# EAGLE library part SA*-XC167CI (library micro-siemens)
16bit Microcontroller with MAC Unit 256KB Flash
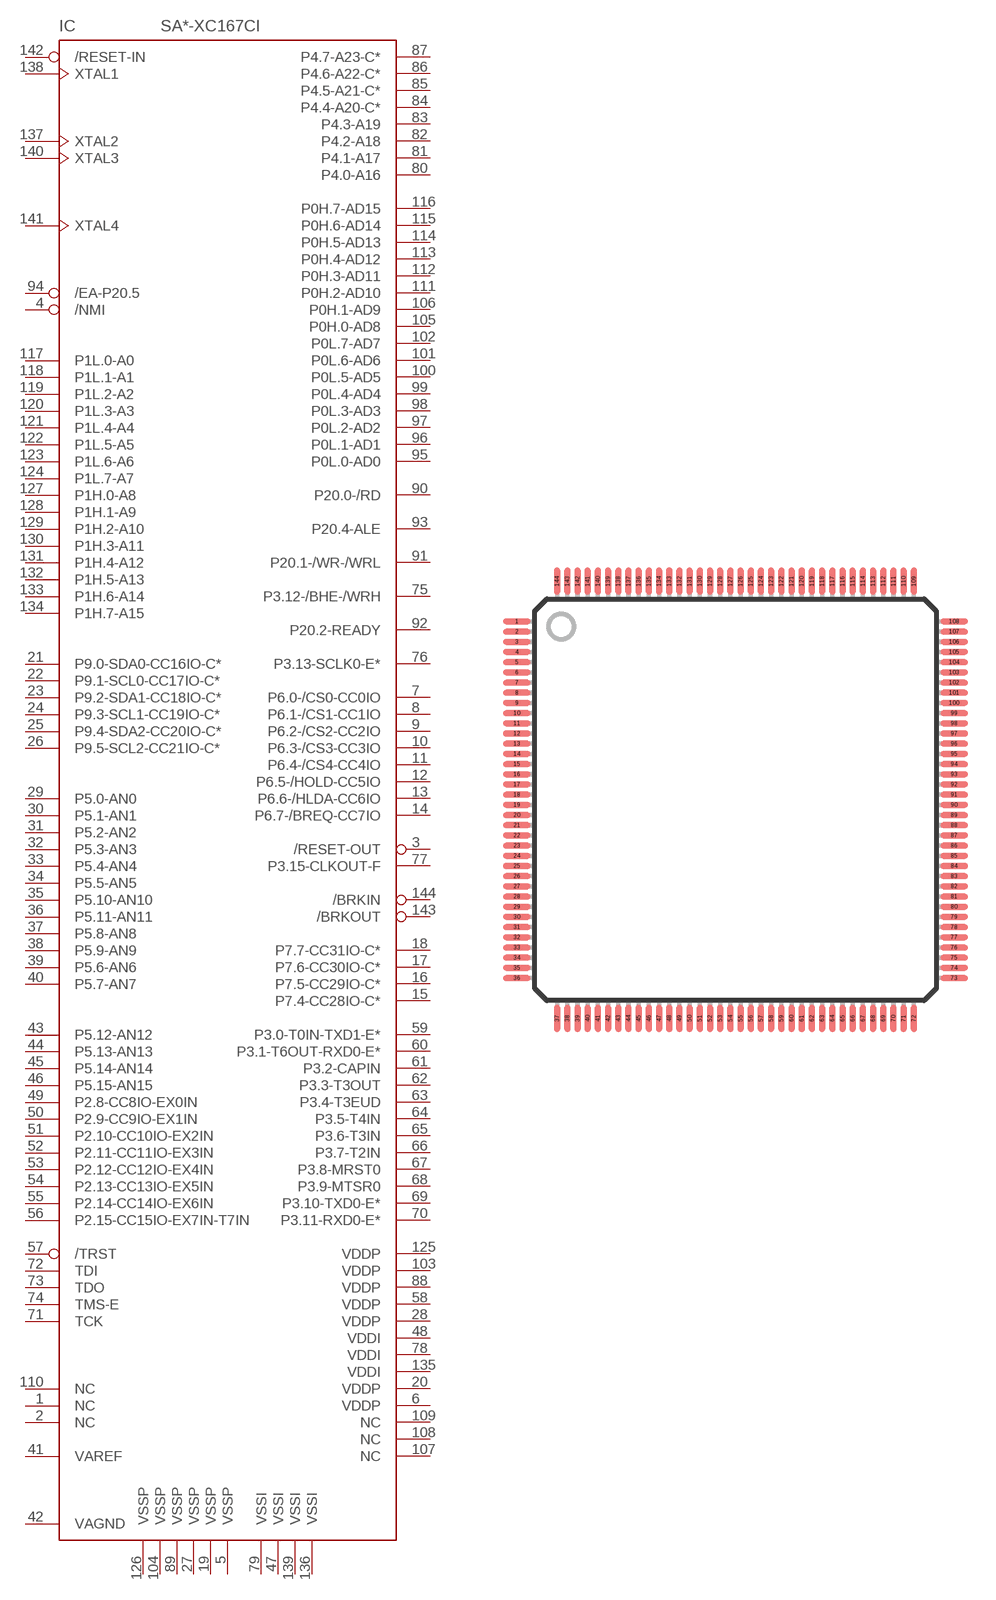
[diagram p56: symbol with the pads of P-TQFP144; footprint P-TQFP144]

Designator prefix IC

## SAB-XC167CI (OC_FARNELL: unknown; OC_NEWARK: unknown), SAF-XC167CI (OC_FARNELL: unknown; OC_NEWARK: unknown), SAK-XC167CI (OC_FARNELL: unknown; OC_NEWARK: unknown)  [P-TQFP144]
1  NC
2  NC
3  /RESET-OUT
4  /NMI
5  VSSP  pwr
6  VDDP  pwr
7  P6.0-/CS0-CC0IO
8  P6.1-/CS1-CC1IO
9  P6.2-/CS2-CC2IO
10  P6.3-/CS3-CC3IO
11  P6.4-/CS4-CC4IO
12  P6.5-/HOLD-CC5IO
13  P6.6-/HLDA-CC6IO
14  P6.7-/BREQ-CC7IO
15  P7.4-CC28IO-C*
16  P7.5-CC29IO-C*
17  P7.6-CC30IO-C*
18  P7.7-CC31IO-C*
19  VSSP  pwr
20  VDDP  pwr
21  P9.0-SDA0-CC16IO-C*
22  P9.1-SCL0-CC17IO-C*
23  P9.2-SDA1-CC18IO-C*
24  P9.3-SCL1-CC19IO-C*
25  P9.4-SDA2-CC20IO-C*
26  P9.5-SCL2-CC21IO-C*
27  VSSP  pwr
28  VDDP  pwr
29  P5.0-AN0
30  P5.1-AN1
31  P5.2-AN2
32  P5.3-AN3
33  P5.4-AN4
34  P5.5-AN5
35  P5.10-AN10
36  P5.11-AN11
37  P5.8-AN8
38  P5.9-AN9
39  P5.6-AN6
40  P5.7-AN7
41  VAREF
42  VAGND
43  P5.12-AN12
44  P5.13-AN13
45  P5.14-AN14
46  P5.15-AN15
47  VSSI  pwr
48  VDDI  pwr
49  P2.8-CC8IO-EX0IN
50  P2.9-CC9IO-EX1IN
51  P2.10-CC10IO-EX2IN
52  P2.11-CC11IO-EX3IN
53  P2.12-CC12IO-EX4IN
54  P2.13-CC13IO-EX5IN
55  P2.14-CC14IO-EX6IN
56  P2.15-CC15IO-EX7IN-T7IN
57  /TRST
58  VDDP  pwr
59  P3.0-T0IN-TXD1-E*
60  P3.1-T6OUT-RXD0-E*
61  P3.2-CAPIN
62  P3.3-T3OUT
63  P3.4-T3EUD
64  P3.5-T4IN
65  P3.6-T3IN
66  P3.7-T2IN
67  P3.8-MRST0
68  P3.9-MTSR0
69  P3.10-TXD0-E*
70  P3.11-RXD0-E*
71  TCK
72  TDI
73  TDO
74  TMS-E
75  P3.12-/BHE-/WRH
76  P3.13-SCLK0-E*
77  P3.15-CLKOUT-F
78  VDDI  pwr
79  VSSI  pwr
80  P4.0-A16
81  P4.1-A17
82  P4.2-A18
83  P4.3-A19
84  P4.4-A20-C*
85  P4.5-A21-C*
86  P4.6-A22-C*
87  P4.7-A23-C*
88  VDDP  pwr
89  VSSP  pwr
90  P20.0-/RD
91  P20.1-/WR-/WRL
92  P20.2-READY
93  P20.4-ALE
94  /EA-P20.5
95  P0L.0-AD0
96  P0L.1-AD1
97  P0L.2-AD2
98  P0L.3-AD3
99  P0L.4-AD4
100  P0L.5-AD5
101  P0L.6-AD6
102  P0L.7-AD7
103  VDDP  pwr
104  VSSP  pwr
105  P0H.0-AD8
106  P0H.1-AD9
107  NC
108  NC
109  NC
110  NC
111  P0H.2-AD10
112  P0H.3-AD11
113  P0H.4-AD12
114  P0H.5-AD13
115  P0H.6-AD14
116  P0H.7-AD15
117  P1L.0-A0
118  P1L.1-A1
119  P1L.2-A2
120  P1L.3-A3
121  P1L.4-A4
122  P1L.5-A5
123  P1L.6-A6
124  P1L.7-A7
125  VDDP  pwr
126  VSSP  pwr
127  P1H.0-A8
128  P1H.1-A9
129  P1H.2-A10
130  P1H.3-A11
131  P1H.4-A12
132  P1H.5-A13
133  P1H.6-A14
134  P1H.7-A15
135  VDDI  pwr
136  VSSI  pwr
137  XTAL2
138  XTAL1
139  VSSI  pwr
140  XTAL3
141  XTAL4
142  /RESET-IN
143  /BRKOUT
144  /BRKIN

## Footprint P-TQFP144 (pad centres in mm)
P-TQFP144 with rounded pads
smd 1.35 x 0.29: 1 -10.725,8.75; 2 -10.725,8.25; 3 -10.725,7.75; 4 -10.725,7.25; 5 -10.725,6.75; 6 -10.725,6.25; 7 -10.725,5.75; 8 -10.725,5.25; 9 -10.725,4.75; 10 -10.725,4.25; 11 -10.725,3.75; 12 -10.725,3.25; 13 -10.725,2.75; 14 -10.725,2.25; 15 -10.725,1.75; 16 -10.725,1.25; 17 -10.725,0.75; 18 -10.725,0.25; 19 -10.725,-0.25; 20 -10.725,-0.75; 21 -10.725,-1.25; 22 -10.725,-1.75; 23 -10.725,-2.25; 24 -10.725,-2.75; 25 -10.725,-3.25; 26 -10.725,-3.75; 27 -10.725,-4.25; 28 -10.725,-4.75; 29 -10.725,-5.25; 30 -10.725,-5.75; 31 -10.725,-6.25; 32 -10.725,-6.75; 33 -10.725,-7.25; 34 -10.725,-7.75; 35 -10.725,-8.25; 36 -10.725,-8.75; 73 10.725,-8.75; 74 10.725,-8.25; 75 10.725,-7.75; 76 10.725,-7.25; 77 10.725,-6.75; 78 10.725,-6.25; 79 10.725,-5.75; 80 10.725,-5.25; 81 10.725,-4.75; 82 10.725,-4.25; 83 10.725,-3.75; 84 10.725,-3.25; 85 10.725,-2.75; 86 10.725,-2.25; 87 10.725,-1.75; 88 10.725,-1.25; 89 10.725,-0.75; 90 10.725,-0.25; 91 10.725,0.25; 92 10.725,0.75; 93 10.725,1.25; 94 10.725,1.75; 95 10.725,2.25; 96 10.725,2.75; 97 10.725,3.25; 98 10.725,3.75; 99 10.725,4.25; 100 10.725,4.75; 101 10.725,5.25; 102 10.725,5.75; 103 10.725,6.25; 104 10.725,6.75; 105 10.725,7.25; 106 10.725,7.75; 107 10.725,8.25; 108 10.725,8.75
smd 0.29 x 1.35: 37 -8.75,-10.725; 38 -8.25,-10.725; 39 -7.75,-10.725; 40 -7.25,-10.725; 41 -6.75,-10.725; 42 -6.25,-10.725; 43 -5.75,-10.725; 44 -5.25,-10.725; 45 -4.75,-10.725; 46 -4.25,-10.725; 47 -3.75,-10.725; 48 -3.25,-10.725; 49 -2.75,-10.725; 50 -2.25,-10.725; 51 -1.75,-10.725; 52 -1.25,-10.725; 53 -0.75,-10.725; 54 -0.25,-10.725; 55 0.25,-10.725; 56 0.75,-10.725; 57 1.25,-10.725; 58 1.75,-10.725; 59 2.25,-10.725; 60 2.75,-10.725; 61 3.25,-10.725; 62 3.75,-10.725; 63 4.25,-10.725; 64 4.75,-10.725; 65 5.25,-10.725; 66 5.75,-10.725; 67 6.25,-10.725; 68 6.75,-10.725; 69 7.25,-10.725; 70 7.75,-10.725; 71 8.25,-10.725; 72 8.75,-10.725; 109 8.75,10.725; 110 8.25,10.725; 111 7.75,10.725; 112 7.25,10.725; 113 6.75,10.725; 114 6.25,10.725; 115 5.75,10.725; 116 5.25,10.725; 117 4.75,10.725; 118 4.25,10.725; 119 3.75,10.725; 120 3.25,10.725; 121 2.75,10.725; 122 2.25,10.725; 123 1.75,10.725; 124 1.25,10.725; 125 0.75,10.725; 126 0.25,10.725; 127 -0.25,10.725; 128 -0.75,10.725; 129 -1.25,10.725; 130 -1.75,10.725; 131 -2.25,10.725; 132 -2.75,10.725; 133 -3.25,10.725; 134 -3.75,10.725; 135 -4.25,10.725; 136 -4.75,10.725; 137 -5.25,10.725; 138 -5.75,10.725; 139 -6.25,10.725; 140 -6.75,10.725; 141 -7.25,10.725; 142 -7.75,10.725; 143 -8.25,10.725; 144 -8.75,10.725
